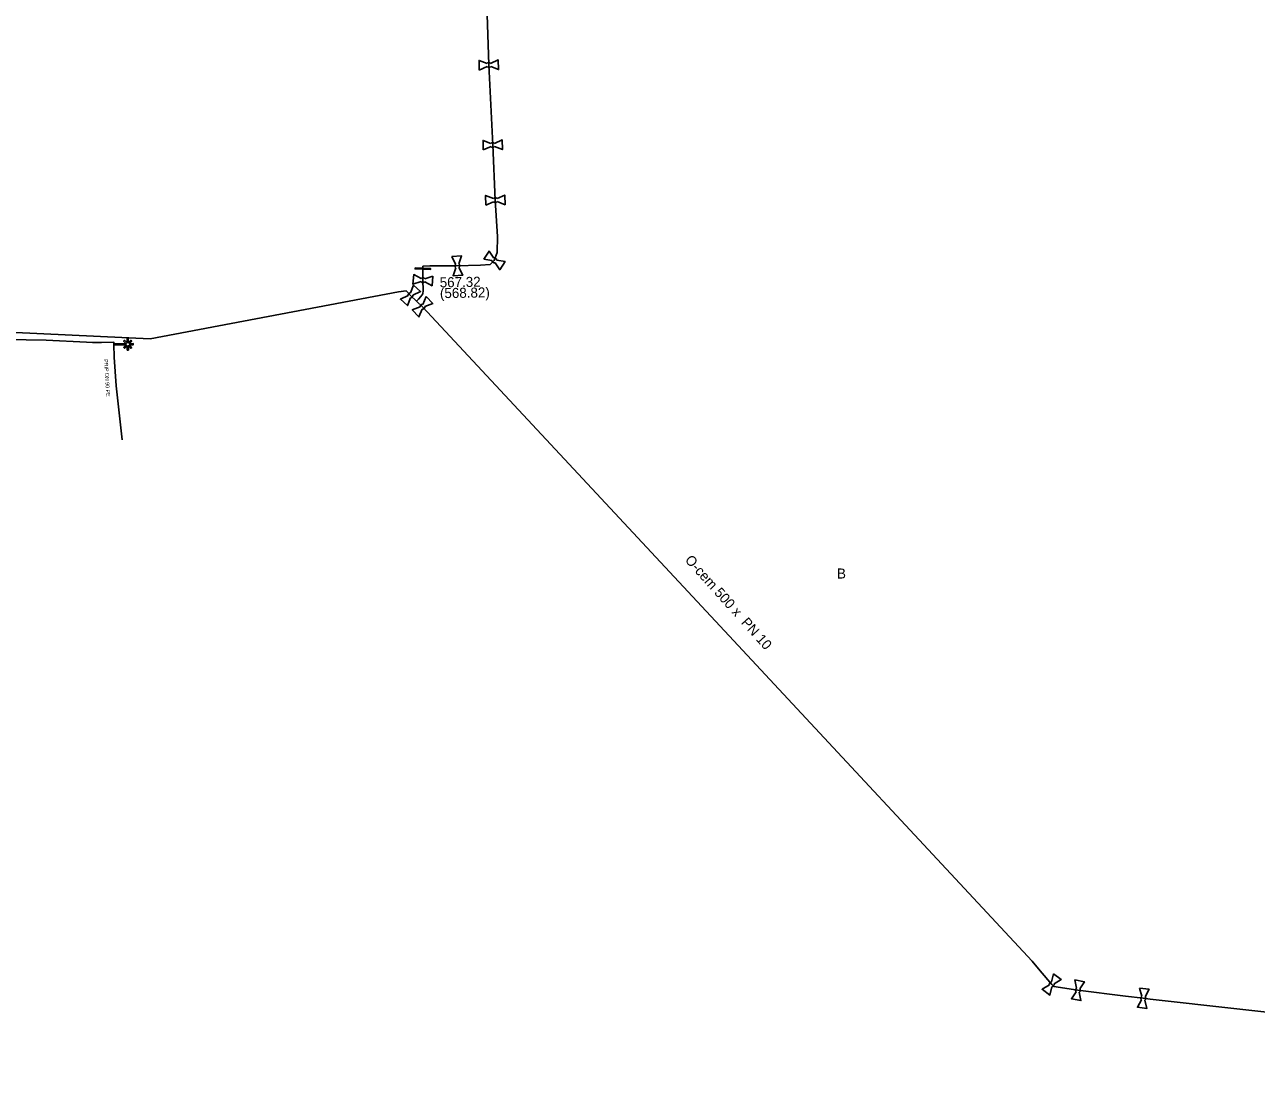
# Model space of a CAD drawing. Extents: x -643842 to -636370, y -1119190 to -1110210.
# Drawn here: x -641769.3 to -641609.4, y -1114520.8 to -1114385.1 of the extents above; entities that cross this region are included whole.
import ezdxf

# ---------------------------------------------------------------- set-up
doc = ezdxf.new("R2010")
doc.units = 0
for name, color, linetype in [('2', 7, 'Continuous'), ('22', 7, 'Continuous'), ('Default', 7, 'Continuous'), ('Level 16', 7, 'Continuous'), ('Level 19', 7, 'Continuous'), ('Level 20', 7, 'Continuous'), ('Level 21', 7, 'Continuous'), ('Level 23', 7, 'Continuous'), ('Level 27', 7, 'Continuous'), ('Level 28', 7, 'Continuous')]:
    doc.layers.add(name, color=color, linetype=linetype)

msp = doc.modelspace()

# ---------------------------------------------------------------- linework, layer by layer
at = {"layer": '2'}
msp.add_lwpolyline([(-641755.75, -1114426.56), (-641755.21, -1114426.55), (-641755.21, -1114426.7), (-641755.74, -1114426.71), (-641755.41, -1114427.04), (-641755.52, -1114427.15), (-641755.85, -1114426.83), (-641755.84, -1114427.4), (-641756, -1114427.4), (-641756.01, -1114426.82), (-641756.34, -1114427.16), (-641756.45, -1114427.05), (-641756.13, -1114426.72), (-641757.71, -1114426.74), (-641757.71, -1114426.58), (-641756.12, -1114426.56), (-641756.46, -1114426.23), (-641756.35, -1114426.12), (-641756.01, -1114426.45), (-641756.02, -1114425.87), (-641755.86, -1114425.86), (-641755.86, -1114426.44), (-641755.53, -1114426.11), (-641755.42, -1114426.22), (-641755.75, -1114426.56)], dxfattribs=at)
at = {"layer": 'Default'}
for points in [[(-641709.28, -1114390.16), (-641709.25, -1114390.12), (-641709.2, -1114390.1), (-641709.13, -1114390.05), (-641709.05, -1114390.05), (-641708.97, -1114390.05), (-641708.89, -1114390.09), (-641708.84, -1114390.11), (-641708.81, -1114390.15)], [(-641708.8, -1114390.56), (-641708.83, -1114390.6), (-641708.88, -1114390.63), (-641708.95, -1114390.67), (-641709.03, -1114390.68), (-641709.12, -1114390.68), (-641709.19, -1114390.64), (-641709.24, -1114390.61), (-641709.28, -1114390.57)], [(-641708.77, -1114400.54), (-641708.74, -1114400.5), (-641708.69, -1114400.48), (-641708.62, -1114400.43), (-641708.53, -1114400.43), (-641708.45, -1114400.43), (-641708.38, -1114400.47), (-641708.33, -1114400.5), (-641708.3, -1114400.54)], [(-641708.29, -1114400.94), (-641708.32, -1114400.98), (-641708.37, -1114401.01), (-641708.44, -1114401.06), (-641708.52, -1114401.06), (-641708.6, -1114401.06), (-641708.68, -1114401.02), (-641708.73, -1114400.99), (-641708.76, -1114400.95)], [(-641708.45, -1114407.71), (-641708.42, -1114407.67), (-641708.37, -1114407.65), (-641708.3, -1114407.6), (-641708.21, -1114407.6), (-641708.13, -1114407.6), (-641708.06, -1114407.64), (-641708.01, -1114407.66), (-641707.97, -1114407.7)], [(-641707.97, -1114408.11), (-641708, -1114408.15), (-641708.05, -1114408.18), (-641708.12, -1114408.22), (-641708.2, -1114408.23), (-641708.28, -1114408.23), (-641708.36, -1114408.19), (-641708.41, -1114408.16), (-641708.44, -1114408.12)], [(-641708.24, -1114416.04), (-641708.29, -1114416.05), (-641708.35, -1114416.05), (-641708.43, -1114416.04), (-641708.5, -1114416), (-641708.57, -1114415.95), (-641708.61, -1114415.87), (-641708.63, -1114415.83), (-641708.64, -1114415.77)], [(-641708.41, -1114415.43), (-641708.36, -1114415.42), (-641708.31, -1114415.42), (-641708.22, -1114415.43), (-641708.15, -1114415.47), (-641708.08, -1114415.52), (-641708.05, -1114415.59), (-641708.02, -1114415.64), (-641708.02, -1114415.7)], [(-641713.32, -1114416.7), (-641713.37, -1114416.67), (-641713.4, -1114416.62), (-641713.44, -1114416.55), (-641713.45, -1114416.47), (-641713.45, -1114416.39), (-641713.41, -1114416.31), (-641713.39, -1114416.26), (-641713.35, -1114416.22)], [(-641712.95, -1114416.2), (-641712.9, -1114416.23), (-641712.87, -1114416.28), (-641712.83, -1114416.35), (-641712.82, -1114416.43), (-641712.82, -1114416.51), (-641712.86, -1114416.59), (-641712.88, -1114416.64), (-641712.92, -1114416.67)], [(-641717.37, -1114418.53), (-641717.41, -1114418.57), (-641717.46, -1114418.59), (-641717.54, -1114418.63), (-641717.62, -1114418.62), (-641717.7, -1114418.62), (-641717.77, -1114418.57), (-641717.81, -1114418.54), (-641717.84, -1114418.49)], [(-641717.81, -1114418.09), (-641717.77, -1114418.05), (-641717.72, -1114418.03), (-641717.65, -1114417.99), (-641717.57, -1114418), (-641717.49, -1114418.01), (-641717.41, -1114418.05), (-641717.37, -1114418.08), (-641717.34, -1114418.13)], [(-641719.53, -1114420.32), (-641719.54, -1114420.26), (-641719.52, -1114420.21), (-641719.51, -1114420.13), (-641719.45, -1114420.07), (-641719.39, -1114420.01), (-641719.31, -1114419.98), (-641719.26, -1114419.96), (-641719.21, -1114419.97)], [(-641718.91, -1114420.24), (-641718.9, -1114420.3), (-641718.91, -1114420.35), (-641718.93, -1114420.43), (-641718.99, -1114420.49), (-641719.05, -1114420.55), (-641719.13, -1114420.58), (-641719.18, -1114420.59), (-641719.23, -1114420.59)], [(-641717.96, -1114421.78), (-641717.97, -1114421.73), (-641717.95, -1114421.67), (-641717.93, -1114421.59), (-641717.87, -1114421.54), (-641717.81, -1114421.48), (-641717.73, -1114421.46), (-641717.67, -1114421.44), (-641717.62, -1114421.45)], [(-641717.34, -1114421.74), (-641717.33, -1114421.79), (-641717.35, -1114421.84), (-641717.37, -1114421.93), (-641717.43, -1114421.98), (-641717.49, -1114422.04), (-641717.57, -1114422.06), (-641717.63, -1114422.08), (-641717.68, -1114422.07)], [(-641636.26, -1114509.85), (-641636.28, -1114509.8), (-641636.27, -1114509.75), (-641636.26, -1114509.66), (-641636.21, -1114509.6), (-641636.16, -1114509.53), (-641636.09, -1114509.49), (-641636.04, -1114509.47), (-641635.98, -1114509.47)], [(-641635.65, -1114509.71), (-641635.64, -1114509.76), (-641635.65, -1114509.81), (-641635.66, -1114509.9), (-641635.71, -1114509.96), (-641635.76, -1114510.03), (-641635.83, -1114510.06), (-641635.88, -1114510.09), (-641635.93, -1114510.09)], [(-641632.8, -1114510.74), (-641632.84, -1114510.69), (-641632.85, -1114510.64), (-641632.88, -1114510.56), (-641632.87, -1114510.48), (-641632.85, -1114510.4), (-641632.8, -1114510.34), (-641632.76, -1114510.29), (-641632.72, -1114510.27)], [(-641632.31, -1114510.34), (-641632.28, -1114510.38), (-641632.26, -1114510.43), (-641632.24, -1114510.52), (-641632.25, -1114510.6), (-641632.27, -1114510.68), (-641632.32, -1114510.74), (-641632.36, -1114510.78), (-641632.4, -1114510.81)], [(-641624.3, -1114511.8), (-641624.34, -1114511.76), (-641624.36, -1114511.71), (-641624.39, -1114511.64), (-641624.38, -1114511.55), (-641624.37, -1114511.47), (-641624.32, -1114511.4), (-641624.29, -1114511.36), (-641624.25, -1114511.33)], [(-641623.84, -1114511.38), (-641623.8, -1114511.42), (-641623.78, -1114511.46), (-641623.75, -1114511.54), (-641623.76, -1114511.63), (-641623.77, -1114511.71), (-641623.82, -1114511.77), (-641623.85, -1114511.82), (-641623.89, -1114511.85)]]:
    msp.add_open_spline(points, degree=3, dxfattribs=at)
at = {"layer": 'Level 16'}
msp.add_lwpolyline([(-641718.61, -1114416.72), (-641716.61, -1114416.8), (-641716.61, -1114416.92), (-641718.61, -1114416.84), (-641718.61, -1114416.72)], dxfattribs=at)
at = {"layer": 'Level 21'}
for points in [[(-641718.42, -1114421.03), (-641718.16, -1114420.79), (-641717.86, -1114420.44), (-641717.6, -1114420.1), (-641717.56, -1114419.63), (-641717.59, -1114418.31), (-641717.61, -1114416.82), (-641717.61, -1114416.49), (-641716.7, -1114416.45), (-641713.28, -1114416.45), (-641710.11, -1114416.36), (-641708.89, -1114416.28), (-641708.33, -1114415.74), (-641707.98, -1114414.71), (-641707.9, -1114412.65), (-641708.21, -1114407.91), (-641708.53, -1114400.74), (-641709.04, -1114390.36), (-641709.34, -1114381.17)], [(-641718.42, -1114421.03), (-641719.22, -1114420.28), (-641719.79, -1114419.69), (-641720.77, -1114419.84), (-641753.01, -1114425.92), (-641777.9, -1114424.76), (-641778.78, -1114424.71), (-641780.03, -1114424.65), (-641780.7, -1114424.61), (-641793.29, -1114423.95), (-641806.12, -1114423.27), (-641821.86, -1114422.3), (-641843.01, -1114418.5), (-641856.42, -1114414), (-641861.09, -1114412.7), (-641861.77, -1114412.49)], [(-641339.44, -1114515.59), (-641438.93, -1114518.43), (-641439.86, -1114518.45), (-641441.04, -1114518.48), (-641441.65, -1114518.49), (-641501.75, -1114520.23), (-641541.97, -1114520.82), (-641542.44, -1114520.75), (-641543.64, -1114520.58), (-641623.18, -1114511.71), (-641624.07, -1114511.59), (-641626.37, -1114511.31), (-641632.56, -1114510.54), (-641635.68, -1114510.06), (-641635.96, -1114509.78), (-641637.47, -1114508.03), (-641638.5, -1114506.77), (-641677.84, -1114464.5), (-641717.65, -1114421.76), (-641718.42, -1114421.03)]]:
    msp.add_lwpolyline(points, dxfattribs=at)
at = {"layer": 'Level 23'}
for points in [[(-641757.71, -1114426.66), (-641757.74, -1114426.35), (-641759.32, -1114426.41), (-641760.51, -1114426.39), (-641761.26, -1114426.36), (-641766.52, -1114426.12), (-641771.69, -1114426.03), (-641777.97, -1114425.9), (-641781.01, -1114425.78), (-641784.86, -1114425.39), (-641790.35, -1114425.68), (-641793.29, -1114426.45), (-641795.68, -1114427.52), (-641798.08, -1114429.34), (-641800.27, -1114431.39), (-641804.6, -1114435.49), (-641805.32, -1114435.56), (-641805.49, -1114435.56)], [(-641757.71, -1114426.66), (-641757.69, -1114428.29), (-641757.41, -1114432.02), (-641756.67, -1114439.06)]]:
    msp.add_lwpolyline(points, dxfattribs=at)
at = {"layer": 'Level 28'}
for points in [[(-641710.28, -1114391.01), (-641710.3, -1114389.76), (-641709.28, -1114390.16)], [(-641708.81, -1114390.15), (-641707.81, -1114389.71), (-641707.78, -1114390.96), (-641708.8, -1114390.56)], [(-641709.28, -1114390.57), (-641710.28, -1114391.01)], [(-641709.76, -1114401.4), (-641709.79, -1114400.15), (-641708.77, -1114400.54)], [(-641708.76, -1114400.95), (-641709.76, -1114401.4)], [(-641708.3, -1114400.54), (-641707.29, -1114400.09), (-641707.27, -1114401.34), (-641708.29, -1114400.94)], [(-641709.44, -1114408.56), (-641709.47, -1114407.31), (-641708.45, -1114407.71)], [(-641707.97, -1114407.7), (-641706.97, -1114407.26), (-641706.94, -1114408.51), (-641707.97, -1114408.11)], [(-641708.44, -1114408.12), (-641709.44, -1114408.56)], [(-641713.84, -1114415.24), (-641712.59, -1114415.16), (-641712.95, -1114416.2)], [(-641713.35, -1114416.22), (-641713.84, -1114415.24)], [(-641709.71, -1114415.57), (-641709.02, -1114414.52), (-641708.41, -1114415.43)], [(-641708.64, -1114415.77), (-641709.71, -1114415.57)], [(-641708.02, -1114415.7), (-641706.94, -1114415.9), (-641707.63, -1114416.95), (-641708.24, -1114416.04)], [(-641712.92, -1114416.67), (-641712.43, -1114417.66), (-641713.68, -1114417.74), (-641713.32, -1114416.7)], [(-641719.21, -1114419.97), (-641718.83, -1114418.94)], [(-641718.83, -1114418.94), (-641717.91, -1114419.78), (-641718.91, -1114420.24)], [(-641717.84, -1114418.49), (-641718.89, -1114418.83), (-641718.79, -1114417.59), (-641717.81, -1114418.09)], [(-641716.3, -1114417.79), (-641716.4, -1114419.04), (-641717.37, -1114418.53)], [(-641717.34, -1114418.13), (-641716.3, -1114417.79)], [(-641719.23, -1114420.59), (-641719.61, -1114421.62), (-641720.53, -1114420.78), (-641719.53, -1114420.32)], [(-641717.62, -1114421.45), (-641717.19, -1114420.44)], [(-641717.19, -1114420.44), (-641716.32, -1114421.34), (-641717.34, -1114421.74)], [(-641717.68, -1114422.07), (-641718.11, -1114423.08), (-641718.98, -1114422.18), (-641717.96, -1114421.78)], [(-641635.98, -1114509.47), (-641635.73, -1114508.4)], [(-641635.73, -1114508.4), (-641634.72, -1114509.14), (-641635.65, -1114509.71)], [(-641635.93, -1114510.09), (-641636.19, -1114511.16), (-641637.2, -1114510.42), (-641636.26, -1114509.85)], [(-641632.95, -1114509.2), (-641631.72, -1114509.43), (-641632.31, -1114510.34)], [(-641632.72, -1114510.27), (-641632.95, -1114509.2)], [(-641624.55, -1114510.28), (-641623.31, -1114510.42), (-641623.84, -1114511.38)], [(-641624.25, -1114511.33), (-641624.55, -1114510.28)], [(-641632.4, -1114510.81), (-641632.17, -1114511.88), (-641633.4, -1114511.65), (-641632.8, -1114510.74)], [(-641623.89, -1114511.85), (-641623.59, -1114512.9), (-641624.83, -1114512.76), (-641624.3, -1114511.8)]]:
    msp.add_lwpolyline(points, dxfattribs=at)

# ---------------------------------------------------------------- texts
at = {"layer": '22'}
msp.add_text('PRIP DN 90 PE', height=0.5, rotation=273.5335, dxfattribs=at).set_placement((-641759.01, -1114428.59))
at = {"layer": 'Level 19'}
msp.add_text('B', height=1.3, dxfattribs=at).set_placement((-641663.84, -1114457.06))
at = {"layer": 'Level 20'}
msp.add_text('O-cem 500 x  PN 10', height=1.3, rotation=311.9185, dxfattribs=at).set_placement((-641683.66, -1114454.72))
at = {"layer": 'Level 27'}
for s, p in [('567.32', (-641715.41, -1114419.25)), ('(568.82)', (-641715.38, -1114420.65))]:
    msp.add_text(s, height=1.3, rotation=1, dxfattribs=at).set_placement(p)

doc.saveas('drawing.dxf')
